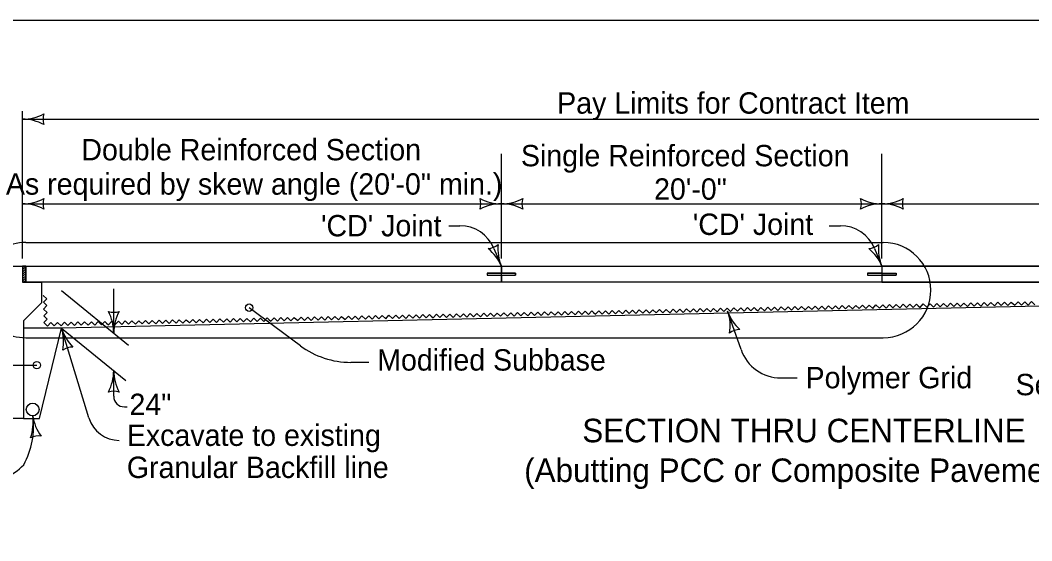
# Model space of a CAD drawing. Extents: x 10130 to 81668, y 5440 to 21644.
# Drawn here: x 14155 to 15102, y 7067 to 7554 of the extents above; entities that cross this region are included whole.
import ezdxf

# ---------------------------------------------------------------- set-up
doc = ezdxf.new("R2010")
doc.units = 0
for name, color, linetype in [('Cell', 7, 'Continuous'), ('dsnStdBlockModified', 7, 'Continuous'), ('dsnStdBlockNotModified', 7, 'Continuous'), ('dsnStdBorder', 7, 'Continuous')]:
    doc.layers.add(name, color=color, linetype=linetype)

msp = doc.modelspace()

# ---------------------------------------------------------------- linework, layer by layer
at = {"layer": 'Cell'}
msp.add_lwpolyline([(13803.17, 7554.12), (16938.17, 7554.12), (16938.17, 5544.12), (13803.17, 5544.12)], close=True, dxfattribs=at)
at = {"layer": 'dsnStdBlockModified'}
for p, q in [((14157.11, 7331.28), (14157.11, 7468.91)), ((14157.11, 7461.48), (15496.58, 7461.48)), ((14605.58, 7331.28), (14605.58, 7429.02)), ((14961.98, 7331.28), (14961.98, 7429.02)), ((14157.11, 7382.28), (14605.58, 7382.28)), ((14605.58, 7382.28), (14961.98, 7382.28)), ((14961.98, 7382.28), (15318.38, 7382.28)), ((14556.31, 7361.85), (14566.66, 7361.85)), ((14912.71, 7361.85), (14923.06, 7361.85)), ((14160.08, 7346.13), (14963.24, 7346.13)), ((14160.08, 7323.85), (14605.58, 7323.86)), ((14160.08, 7308.96), (14160.08, 7323.85)), ((14605.58, 7323.86), (14605.58, 7317.37)), ((14605.58, 7317.37), (14605.58, 7323.86)), ((14605.58, 7323.86), (14961.98, 7323.86)), ((14961.98, 7323.86), (14961.98, 7317.36)), ((14592.22, 7317.36), (14592.21, 7315.5)), ((14618.94, 7317.36), (14592.21, 7317.36)), ((14592.21, 7315.5), (14605.56, 7315.5)), ((14605.58, 7317.37), (14592.22, 7317.36)), ((14592.22, 7317.36), (14605.58, 7317.37)), ((14605.56, 7315.5), (14605.58, 7309.01)), ((14605.58, 7309.01), (14605.56, 7315.5)), ((14605.58, 7315.47), (14618.95, 7315.5)), ((14618.94, 7315.5), (14618.94, 7317.36)), ((14948.61, 7317.36), (14948.61, 7315.5)), ((14961.98, 7317.36), (14948.62, 7317.36)), ((14948.62, 7315.5), (14961.98, 7315.5)), ((14961.98, 7315.5), (14961.98, 7309.01)), ((14174.93, 7308.96), (14160.08, 7308.96)), ((14197.21, 7309.01), (14174.93, 7308.96)), ((14605.58, 7309.01), (14197.21, 7309.01)), ((14961.98, 7309.01), (14605.58, 7309.01)), ((14193.72, 7301.23), (14256.51, 7250.09)), ((14242.54, 7261.48), (14242.54, 7302.67)), ((14417.34, 7249.51), (14369.36, 7285.11)), ((14830.02, 7245.89), (14817.52, 7281.83)), ((14160.08, 7257.03), (14963.24, 7257.03)), ((14193.72, 7265.94), (14254, 7216.86)), ((14219.31, 7181.97), (14193.72, 7265.94)), ((14144.77, 7231.32), (14170.54, 7231.32)), ((14481.4, 7233.91), (14464.53, 7233.91)), ((14242.54, 7202.28), (14242.54, 7226.19)), ((14882.75, 7219.29), (14867.42, 7219.29)), ((14252.54, 7192.28), (14254.98, 7192.28))]:
    msp.add_line(p, q, dxfattribs=at)
for centre, radius, start, end in [((14566.66, 7327.2), 34.65, 22.59071, 90), ((14923.06, 7327.2), 34.65, 22.59071, 90), ((14160.08, 7301.58), 44.55, 89.99958, 270), ((14963.24, 7301.58), 44.55, 270.00108, 90), ((14464.53, 7313.11), 79.2, 233.42435, 270), ((14867.42, 7258.9), 39.6, 199.1769, 270), ((14096.14, 7173.23), 71.28, 330.50921, 8.59146), ((14247.72, 7190.63), 29.7, 196.95347, 270), ((14118.17, 7175.83), 54.97, 270.33247, 316.71985)]:
    msp.add_arc(centre, radius, start, end, dxfattribs=at)
at = {"layer": 'dsnStdBlockNotModified'}
for centre, radius, start, end in [((14157.11, 7503.98), 42.5, 270, 298.07249), ((14192.75, 7461.48), 16.42, 162.26665, 197.73335), ((14157.11, 7418.98), 42.5, 61.92751, 90), ((14157.11, 7424.78), 42.5, 270, 298.07249), ((14157.11, 7339.78), 42.5, 61.92751, 90), ((14192.75, 7382.28), 16.42, 162.26665, 197.73335), ((14569.95, 7382.28), 16.42, 342.26665, 17.73335), ((14605.58, 7424.78), 42.5, 241.92751, 270), ((14605.58, 7339.78), 42.5, 90, 118.07249), ((14605.58, 7424.78), 42.5, 270, 298.07249), ((14605.58, 7339.78), 42.5, 61.92751, 90), ((14641.22, 7382.28), 16.42, 162.26665, 197.73335), ((14926.35, 7382.28), 16.42, 342.26665, 17.73335), ((14961.98, 7424.78), 42.5, 241.92751, 270), ((14961.98, 7339.78), 42.5, 90, 118.07249), ((14961.98, 7424.78), 42.5, 270, 298.07249), ((14961.98, 7339.78), 42.5, 61.92751, 90), ((14997.62, 7382.28), 16.42, 162.26665, 197.73335), ((14591.89, 7356.75), 16.42, 274.86526, 310.33197), ((14644.82, 7340.19), 42.5, 174.52613, 202.59862), ((14948.29, 7356.75), 16.42, 274.86526, 310.33197), ((15001.22, 7340.19), 42.5, 174.52613, 202.59862), ((14566.35, 7307.52), 42.5, 22.59862, 50.6711), ((14922.75, 7307.52), 42.5, 22.59862, 50.6711), ((14857.66, 7295.79), 42.5, 199.17443, 227.24692), ((14777.38, 7267.87), 42.5, 351.10194, 19.17443), ((14234.37, 7278.33), 42.5, 196.95157, 225.02406), ((14153.07, 7253.55), 42.5, 348.87908, 16.95157), ((14829.22, 7248.17), 16.42, 91.44108, 126.90778), ((14204.11, 7231.85), 16.42, 89.21821, 124.68492), ((14200.04, 7226.19), 42.5, 331.92751, 360), ((14285.04, 7226.19), 42.5, 180, 208.07249), ((14242.54, 7190.55), 16.42, 72.26665, 107.73335), ((14124.6, 7177.53), 42.5, 340.51897, 8.59146), ((14208.65, 7190.23), 42.5, 188.59146, 216.66395), ((14171.95, 7148.64), 16.42, 80.85811, 116.32481)]:
    msp.add_arc(centre, radius, start, end, dxfattribs=at)
at = {"layer": 'dsnStdBorder'}
for p, q in [((14598.65, 7340.51), (14605.58, 7323.85)), ((14955.05, 7340.51), (14961.98, 7323.85)), ((14128.89, 7323.85), (14157.11, 7323.85)), ((14157.11, 7323.85), (14157.11, 7308.9)), ((14160.08, 7323.85), (14157.11, 7323.85)), ((14157.11, 7322.58), (14157.98, 7323.45)), ((14157.11, 7320.48), (14160.08, 7323.45)), ((14160.08, 7323.45), (14157.11, 7323.45)), ((14160.08, 7323.85), (14160.08, 7308.9)), ((14160.08, 7323.85), (15314.99, 7323.85)), ((14605.58, 7309), (14605.58, 7323.85)), ((15315, 7323.86), (14961.98, 7323.86)), ((14961.98, 7323.86), (14961.98, 7317.36)), ((14961.98, 7323.85), (14961.98, 7309)), ((14157.11, 7318.38), (14160.08, 7321.35)), ((14157.11, 7316.28), (14160.08, 7319.25)), ((14157.11, 7314.18), (14160.08, 7317.15)), ((14157.11, 7312.08), (14160.08, 7315.05)), ((14592.21, 7317.36), (14618.94, 7317.36)), ((14592.21, 7317.36), (14592.21, 7315.5)), ((14592.21, 7315.5), (14618.94, 7315.5)), ((14618.94, 7317.36), (14618.94, 7315.5)), ((14948.61, 7317.36), (14975.34, 7317.36)), ((14948.61, 7317.36), (14948.61, 7315.5)), ((14948.61, 7315.5), (14975.34, 7315.5)), ((14961.98, 7317.36), (14975.34, 7317.36)), ((14975.34, 7315.5), (14961.98, 7315.5)), ((14961.98, 7315.5), (14961.98, 7309.01)), ((14975.34, 7317.36), (14975.34, 7315.5)), ((14975.34, 7317.36), (14975.34, 7315.5)), ((14157.11, 7309.98), (14160.08, 7312.95)), ((14157.11, 7308.9), (14174.93, 7308.9)), ((14158.14, 7308.9), (14160.08, 7310.85)), ((15301.31, 7309), (14160.08, 7309)), ((14197.2, 7309), (14173.95, 7308.96)), ((14174.93, 7308.96), (14174.93, 7289.7)), ((14961.98, 7309.01), (15301.31, 7309.01)), ((14174.93, 7289.7), (14158.13, 7272.9)), ((15310.95, 7291.18), (14193.72, 7265.94)), ((14158.13, 7272.9), (14158.13, 7181.29)), ((14193.72, 7265.94), (14158.13, 7265.94)), ((14173.03, 7181.29), (14193.72, 7265.94)), ((14158.13, 7181.29), (14102.16, 7181.29)), ((14158.13, 7181.29), (14173.03, 7181.29))]:
    msp.add_line(p, q, dxfattribs=at)
for points in [[(14961.98, 7323.86), (14961.98, 7323.86)], [(14178.88, 7269.5), (14177.14, 7271.16), (14180.24, 7274.4), (14177, 7277.5), (14180.09, 7280.74), (14176.85, 7283.83), (14179.94, 7287.07), (14176.7, 7290.16), (14179.79, 7293.41), (14176.55, 7296.5), (14176.7, 7296.65)], [(14768.01, 7282.1), (14769.62, 7280.55), (14772.72, 7283.78), (14775.96, 7280.68), (14779.06, 7283.92), (14782.29, 7280.82), (14785.39, 7284.05), (14788.63, 7280.95), (14791.73, 7284.19), (14794.96, 7281.09), (14798.06, 7284.33), (14801.29, 7281.22), (14804.4, 7284.46), (14807.63, 7281.36), (14810.73, 7284.6), (14813.97, 7281.49), (14817.06, 7284.73), (14820.3, 7281.63), (14823.4, 7284.86), (14826.63, 7281.77), (14829.73, 7285), (14832.97, 7281.9), (14836.07, 7285.14), (14839.3, 7282.04), (14842.4, 7285.27), (14844.02, 7283.72)], [(14844.02, 7283.72), (14845.64, 7282.17), (14848.74, 7285.41), (14851.97, 7282.31), (14855.07, 7285.55), (14858.31, 7282.44), (14861.41, 7285.68), (14864.64, 7282.58), (14867.74, 7285.81), (14870.97, 7282.71), (14874.08, 7285.95), (14877.31, 7282.85), (14880.41, 7286.08), (14883.65, 7282.99), (14886.74, 7286.22), (14889.98, 7283.12), (14893.08, 7286.36), (14896.31, 7283.26), (14899.41, 7286.49), (14902.65, 7283.39), (14905.75, 7286.63), (14908.98, 7283.53), (14912.08, 7286.76), (14915.32, 7283.66), (14918.42, 7286.9), (14920.04, 7285.35)], [(14920.04, 7285.35), (14921.65, 7283.8), (14924.75, 7287.03), (14927.99, 7283.93), (14931.09, 7287.17), (14934.32, 7284.07), (14937.42, 7287.3), (14940.65, 7284.21), (14943.76, 7287.44), (14946.99, 7284.34), (14950.09, 7287.58), (14953.33, 7284.48), (14956.42, 7287.71), (14959.66, 7284.61), (14962.76, 7287.85), (14965.99, 7284.74), (14969.09, 7287.98), (14972.33, 7284.88), (14975.43, 7288.12), (14978.66, 7285.02), (14981.76, 7288.25), (14985, 7285.15), (14988.1, 7288.39), (14991.33, 7285.29), (14994.43, 7288.52), (14996.05, 7286.97)], [(14996.05, 7286.97), (14997.67, 7285.43), (15000.77, 7288.66), (15004, 7285.56), (15007.1, 7288.8), (15010.33, 7285.7), (15013.44, 7288.93), (15016.67, 7285.83), (15019.77, 7289.07), (15023.01, 7285.96), (15026.1, 7289.2), (15029.34, 7286.1), (15032.44, 7289.34), (15035.67, 7286.24), (15038.77, 7289.47), (15042.01, 7286.37), (15045.11, 7289.61), (15048.34, 7286.51), (15051.44, 7289.74), (15054.68, 7286.65), (15057.78, 7289.88), (15061.01, 7286.78), (15064.11, 7290.02), (15067.35, 7286.92), (15070.45, 7290.15), (15072.06, 7288.6)], [(15072.06, 7288.6), (15073.68, 7287.05), (15076.78, 7290.29), (15080.01, 7287.18), (15083.12, 7290.42), (15086.35, 7287.32), (15089.45, 7290.56), (15092.69, 7287.46), (15095.78, 7290.69), (15099.02, 7287.59), (15102.12, 7290.83), (15105.35, 7287.73)], [(14387.93, 7273.97), (14389.55, 7272.41), (14392.65, 7275.65), (14395.88, 7272.55), (14398.98, 7275.79), (14402.22, 7272.69), (14405.32, 7275.92), (14408.55, 7272.82), (14411.65, 7276.06), (14414.89, 7272.96), (14417.99, 7276.19), (14421.22, 7273.09), (14424.32, 7276.33), (14427.56, 7273.23), (14430.66, 7276.46), (14433.89, 7273.36), (14436.99, 7276.6), (14440.23, 7273.5), (14443.32, 7276.74), (14446.56, 7273.63), (14449.66, 7276.87), (14452.89, 7273.77), (14456, 7277.01), (14459.23, 7273.91), (14462.33, 7277.14), (14463.95, 7275.59)], [(14463.95, 7275.59), (14465.56, 7274.04), (14468.66, 7277.28), (14471.9, 7274.18), (14475, 7277.41), (14478.23, 7274.31), (14481.33, 7277.55), (14484.57, 7274.45), (14487.67, 7277.68), (14490.9, 7274.58), (14494, 7277.82), (14497.24, 7274.72), (14500.34, 7277.96), (14503.57, 7274.85), (14506.67, 7278.09), (14509.91, 7274.99), (14513.01, 7278.23), (14516.24, 7275.13), (14519.34, 7278.36), (14522.57, 7275.26), (14525.68, 7278.5), (14528.91, 7275.4), (14532.01, 7278.63), (14535.25, 7275.53), (14538.34, 7278.77), (14539.96, 7277.22)], [(14539.96, 7277.22), (14541.58, 7275.67), (14544.68, 7278.9), (14547.91, 7275.8), (14551.01, 7279.04), (14554.25, 7275.94), (14557.35, 7279.18), (14560.58, 7276.07), (14563.68, 7279.31), (14566.92, 7276.21), (14570.02, 7279.45), (14573.25, 7276.35), (14576.35, 7279.58), (14579.59, 7276.48), (14582.69, 7279.72), (14585.92, 7276.62), (14589.02, 7279.85), (14592.25, 7276.75), (14595.36, 7279.99), (14598.59, 7276.89), (14601.69, 7280.12), (14604.92, 7277.02), (14608.02, 7280.26), (14611.26, 7277.16), (14614.36, 7280.39), (14615.98, 7278.84)], [(14615.98, 7278.84), (14617.59, 7277.29), (14620.69, 7280.53), (14623.93, 7277.43), (14627.03, 7280.67), (14630.26, 7277.57), (14633.36, 7280.8), (14636.6, 7277.7), (14639.7, 7280.94), (14642.93, 7277.83), (14646.03, 7281.07), (14649.27, 7277.97), (14652.37, 7281.21), (14655.6, 7278.11), (14658.7, 7281.34), (14661.93, 7278.24), (14665.04, 7281.48), (14668.27, 7278.38), (14671.37, 7281.61), (14674.61, 7278.51), (14677.7, 7281.75), (14680.94, 7278.65), (14684.04, 7281.89), (14687.27, 7278.79), (14690.37, 7282.02), (14691.99, 7280.47)], [(14691.99, 7280.47), (14693.61, 7278.92), (14696.71, 7282.16), (14699.94, 7279.05), (14703.04, 7282.29), (14706.28, 7279.19), (14709.38, 7282.42), (14712.61, 7279.33), (14715.71, 7282.56), (14718.95, 7279.46), (14722.05, 7282.7), (14725.28, 7279.6), (14728.38, 7282.83), (14731.61, 7279.73), (14734.72, 7282.97), (14737.95, 7279.87), (14741.05, 7283.11), (14744.28, 7280), (14747.38, 7283.24), (14750.62, 7280.14), (14753.72, 7283.38), (14756.95, 7280.27), (14760.05, 7283.51), (14763.29, 7280.41), (14766.39, 7283.64), (14768.01, 7282.1)], [(14177.27, 7271.04), (14177.28, 7271.05), (14180.51, 7267.95), (14183.61, 7271.18), (14186.85, 7268.08), (14189.95, 7271.32), (14193.18, 7268.22), (14196.28, 7271.45), (14199.51, 7268.35), (14202.61, 7271.59), (14205.85, 7268.49), (14208.95, 7271.72), (14212.18, 7268.62), (14215.28, 7271.86), (14218.52, 7268.76), (14221.62, 7271.99), (14224.85, 7268.89), (14227.95, 7272.13), (14231.19, 7269.03), (14234.29, 7272.26), (14235.9, 7270.71)], [(14235.9, 7270.71), (14237.52, 7269.16), (14240.62, 7272.4), (14243.85, 7269.3), (14246.96, 7272.53), (14250.19, 7269.44), (14253.29, 7272.67), (14256.52, 7269.57), (14259.62, 7272.8), (14262.86, 7269.71), (14265.96, 7272.94), (14269.2, 7269.84), (14272.29, 7273.08), (14275.53, 7269.97), (14278.63, 7273.21), (14281.86, 7270.11), (14284.96, 7273.35), (14288.2, 7270.25), (14291.3, 7273.48), (14294.53, 7270.38), (14297.63, 7273.62), (14300.87, 7270.52), (14303.96, 7273.75), (14307.2, 7270.66), (14310.3, 7273.89), (14311.92, 7272.34)], [(14311.92, 7272.34), (14313.53, 7270.79), (14316.64, 7274.02), (14319.87, 7270.92), (14322.97, 7274.16), (14326.2, 7271.06), (14329.3, 7274.3), (14332.54, 7271.19), (14335.64, 7274.43), (14338.88, 7271.33), (14341.97, 7274.57), (14345.21, 7271.47), (14348.31, 7274.7), (14351.54, 7271.6), (14354.65, 7274.84), (14357.88, 7271.74), (14360.98, 7274.97), (14364.21, 7271.87), (14367.31, 7275.11), (14370.55, 7272.01), (14373.65, 7275.24), (14376.88, 7272.14), (14379.98, 7275.38), (14383.21, 7272.28), (14386.32, 7275.52), (14387.93, 7273.97)]]:
    msp.add_lwpolyline(points, dxfattribs=at)
for centre, radius in [((14369.36, 7285.11), 3.47), ((14170.54, 7231.32), 3.47), ((14166.62, 7189.82), 5.94)]:
    msp.add_circle(centre, radius, dxfattribs=at)
for centre, radius, start, end in [((14242.54, 7297.32), 16.51, 252.26665, 287.73335), ((14199.79, 7261.48), 42.75, 360, 28.07249), ((14242.54, 7297.32), 16.51, 252.26665, 287.73335), ((14199.79, 7261.48), 42.75, 360, 28.07249), ((14285.29, 7261.48), 42.75, 151.92751, 180), ((14285.29, 7261.48), 42.75, 151.92751, 180), ((14252.54, 7202.28), 10, 180, 270)]:
    msp.add_arc(centre, radius, start, end, dxfattribs=at)

# ---------------------------------------------------------------- texts
at = {"layer": 'dsnStdBlockModified'}
for s, height, p in [('Pay Limits for Contract Item', 20, (14657.82, 7466.69)), ('Double Reinforced Section', 20, (14212.2, 7423.01)), ('Single Reinforced Section', 20, (14623.9, 7417.41)), ('As required by skew angle (20\'-0" min.)', 20, (14141.55, 7390.88)), ('20\'-0"', 20, (14748.61, 7386.16)), ("'CD' Joint", 20, (14436.72, 7351.86)), ("'CD' Joint", 20, (14784.9, 7353.18)), ('Modified Subbase', 20, (14489.28, 7226.22)), ('Polymer Grid', 20, (14890.47, 7209.65)), ("See Detail 'C'", 20, (15087.16, 7203.14)), ('24"', 20, (14257.26, 7184.62)), ('Excavate to existing', 20, (14254.82, 7155.72)), ('Granular Backfill line', 20, (14254.82, 7125.72)), ('(Abutting PCC or Composite Pavement)', 22, (14626.96, 7121.97))]:
    msp.add_text(s, height=height, dxfattribs=at).set_placement(p)
at = {"layer": 'dsnStdBorder'}
msp.add_text('SECTION THRU CENTERLINE', height=22, dxfattribs=at).set_placement((14681.37, 7159.15))

doc.saveas('drawing.dxf')
